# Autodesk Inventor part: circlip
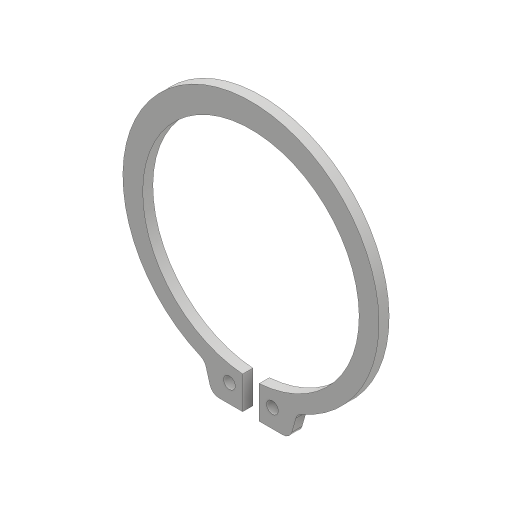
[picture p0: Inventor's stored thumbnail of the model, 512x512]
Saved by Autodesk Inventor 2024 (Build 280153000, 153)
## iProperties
Created: 2016-06
Part Number: circlip
Material: Generic
Document SubType Name: Modeling
Designer: CADCIM
Density: 1 g/cm^3
Appearance: Default
Author: CADCIM
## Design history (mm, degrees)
sketch "Sketch1"
  geometry: L1 (9.52, -25.305)-(8.665, -28.284); L2 (6.743, -29.733)-(1.75, -29.733); L3 (1.75, -29.733)-(1.75, -22.833); L4 (0, 0)-(0, -33.55); L5 (-6.743, -29.733)-(-1.75, -29.733); L6 (-1.75, -29.733)-(-1.75, -22.833); L7 (-9.52, -25.305)-(-8.665, -28.284); C1 r 1.25 at (4.55, -25.815); C2 r 1.25 at (-4.55, -25.815); A1 r 22.9 centre (0, 0) between (1.75, -22.833) and (-1.75, -22.833); A2 r 27.1 centre (0, 0.9) between (10.656, -24.017) and (-10.656, -24.017); A3 r 2 centre (-6.743, -27.733) between (-8.665, -28.284) and (-6.743, -29.733); A4 r 2 centre (-11.442, -25.856) between (-9.52, -25.305) and (-10.656, -24.017); A5 r 2 centre (11.442, -25.856) between (10.656, -24.017) and (9.52, -25.305); A6 r 2 centre (6.743, -27.733) between (6.743, -29.733) and (8.665, -28.284); 12 further points
  constraints: 18 point on circle, 14 end point, 8 centre point, 8 point on line, 8 tangent, 4 equal radius, 4 symmetric about line, 2 coincident, 2 midpoint, 1 horizontal, 1 horizontal alignment, 1 perpendicular, 1 vertical
  dimensions: "d0" = 45.8 diameter of A1; "d4" = 6.9 distance from line of L6.end L5; "d5" = 5.1 distance of point (0, 28) point (0, 22.9); "d6" = 2.5 diameter of C1; "d8" = 2 radius of A3 (derived); "d9" = 2.8 distance from line of C1.centre L3; "d10" = 3.5 distance of L5.end L2.end; "d11" = 27.1 radius of A2; "d14" = 6.5 distance of L5.end point (-8.25, -29.733); "d15" = 32 deg angle of L7 L1
extrude "Extrusion1" new body sketch "Sketch1" distance "d16" = 2.15; taper "d17" = 0 deg
body "Solid1"
other parameters: "d18" = 0
